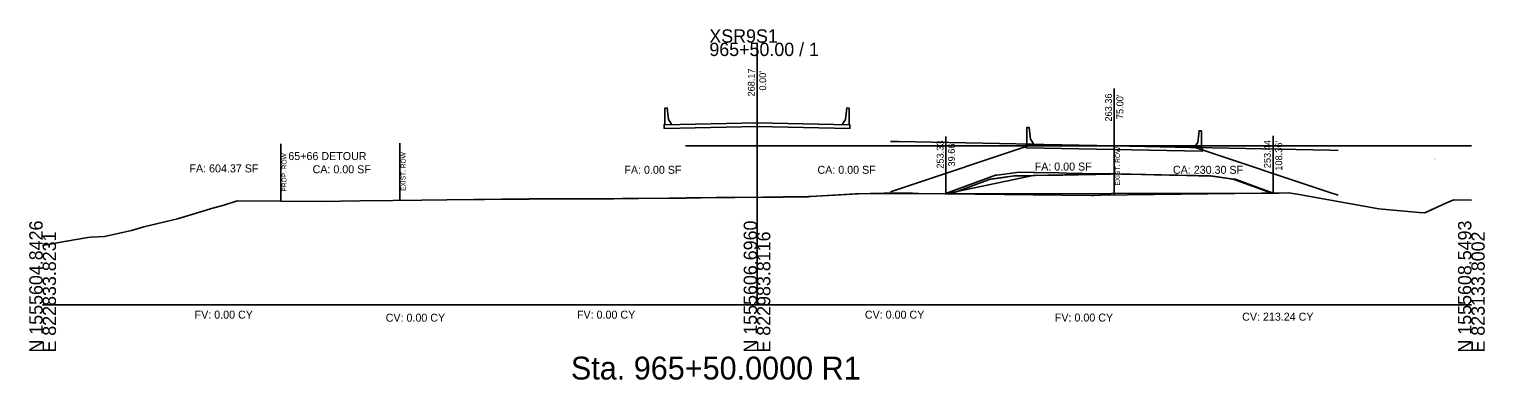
# Model space of a CAD drawing. Extents: x -26 to 823017, y -16 to 1558356.
# Drawn here: x 997.2 to 1302.8, y 4984.3 to 5057.8 of the extents above; entities that cross this region are included whole.
import ezdxf

# ---------------------------------------------------------------- set-up
doc = ezdxf.new("R2010")
doc.units = 0
for name, color, linetype in [('CONST_LV3', 7, 'Continuous'), ('Draft_XS_Grid', 7, 'Continuous'), ('Draft_XS_Text', 7, 'Continuous'), ('DTM_TEMP_DROP', 7, 'Continuous'), ('DTM_X_GROUND', 7, 'Continuous'), ('X_PROFILES_1', 7, 'Continuous'), ('XS_CELL', 7, 'Continuous'), ('XS_P_CONCRETE', 7, 'Continuous'), ('XS_P_GROUND', 7, 'Continuous'), ('XS_P_NULL_POINT', 7, 'Continuous'), ('XS_P_ROW', 7, 'Continuous'), ('XS_P_SUBGRADE_UNDERCUT', 7, 'Continuous'), ('XS_P_TX_CLEARZONE', 7, 'Continuous'), ('XS_SHEET_EW_TX_AREA', 7, 'Continuous'), ('XS_SHEET_EW_TX_VOLUME', 7, 'Continuous'), ('XS_X_ROW', 7, 'Continuous')]:
    doc.layers.add(name, color=color, linetype=linetype)

msp = doc.modelspace()

# ---------------------------------------------------------------- linework, layer by layer
at = {"layer": 'CONST_LV3'}
for points in [[(1135, 5033.36), (1300, 5033.36)], [(1178, 5034.3), (1179.73, 5034.26), (1208, 5033.7), (1208.98, 5033.68), (1225, 5033.36), (1241.02, 5033.04), (1242, 5033.02), (1270.27, 5032.45), (1272, 5032.42)], [(1178, 5023.7), (1179.73, 5024.28), (1208, 5033.7), (1208.98, 5033.68), (1225, 5033.36), (1241.02, 5033.04), (1242, 5033.02), (1270.27, 5023.6), (1272, 5023.02)], [(1000, 5012.44), (1005.04, 5013.35), (1009.5, 5014.16), (1010.12, 5014.21), (1012.96, 5014.34), (1018.65, 5015.63), (1021.23, 5016.35), (1028.33, 5018.07), (1035.97, 5020.35), (1037.84, 5020.84), (1040.84, 5021.8), (1050.02, 5021.76), (1058.5, 5021.71), (1066.61, 5021.81), (1073.56, 5021.9), (1079.59, 5021.97), (1084.87, 5022.03), (1100.77, 5022.2), (1102.16, 5022.22), (1111.63, 5022.24), (1111.86, 5022.24), (1118.28, 5022.23), (1118.45, 5022.23), (1118.74, 5022.24), (1119.81, 5022.27), (1119.96, 5022.28), (1121.71, 5022.34), (1124.87, 5022.33), (1124.89, 5022.33), (1125.13, 5022.34), (1131.5, 5022.42), (1131.5, 5022.42), (1135.22, 5022.44), (1141.41, 5022.52), (1141.41, 5022.52), (1145.28, 5022.54), (1145.31, 5022.54), (1151.32, 5022.62), (1151.32, 5022.62), (1155.39, 5022.63), (1160.81, 5022.7), (1161.24, 5022.71), (1170.63, 5023.29), (1171.28, 5023.33), (1173.79, 5023.34), (1176.66, 5023.44), (1177.7, 5023.47), (1181.91, 5023.42), (1182.64, 5023.41), (1183.67, 5023.4), (1183.69, 5023.4), (1183.94, 5023.4), (1189.42, 5023.33), (1190.69, 5023.32), (1198.96, 5026.35), (1199.2, 5026.39), (1201.37, 5026.68), (1204.02, 5027.04), (1204.53, 5027.05), (1205, 5027.06), (1206.57, 5027.09), (1208, 5027.12), (1208.2, 5027.12), (1208.38, 5027.12), (1211.04, 5027.18), (1211.77, 5027.19), (1213.38, 5027.22), (1214.25, 5027.24), (1214.56, 5027.25), (1215, 5027.26), (1216.82, 5027.29), (1217.46, 5027.31), (1218.38, 5027.32), (1221.08, 5027.38), (1222.1, 5027.4), (1223.38, 5027.42), (1224.26, 5027.44), (1224.91, 5027.46), (1225, 5027.46), (1226.55, 5027.43), (1228.38, 5027.39), (1228.56, 5027.39), (1230.75, 5027.34), (1233.38, 5027.29), (1234.16, 5027.27), (1235, 5027.26), (1236.65, 5027.22), (1238.38, 5027.19), (1240.19, 5027.15), (1242, 5027.12), (1242.7, 5027.1), (1243.38, 5027.09), (1244.21, 5027.07), (1245, 5027.06), (1245.01, 5027.06), (1245.01, 5027.06), (1245.16, 5027.04), (1249.85, 5026.41), (1250.07, 5026.37), (1254.88, 5024.61), (1258.08, 5023.44), (1259.6, 5023.45), (1261.7, 5023.48), (1263.45, 5023.24), (1280.6, 5020.14), (1289.02, 5019.4), (1290.24, 5019.29), (1294.62, 5021.37), (1296.3, 5022.03), (1300, 5021.94)], [(1189.66, 5023.33), (1189.66, 5023.33), (1208, 5027.12)]]:
    msp.add_lwpolyline(points, dxfattribs=at)
at = {"layer": 'DTM_X_GROUND'}
for points in [[(1000, 5012.44), (1005.04, 5013.35), (1009.5, 5014.16), (1010.12, 5014.21), (1012.96, 5014.34), (1018.65, 5015.63), (1021.23, 5016.35), (1028.33, 5018.07), (1035.97, 5020.35), (1037.84, 5020.84), (1040.84, 5021.8), (1050.02, 5021.76), (1058.5, 5021.71), (1066.61, 5021.81), (1073.56, 5021.9), (1079.59, 5021.97), (1084.87, 5022.03), (1102.16, 5022.22), (1111.86, 5022.24), (1118.45, 5022.23), (1121.71, 5022.34), (1124.89, 5022.33), (1125.13, 5022.34), (1131.5, 5022.42), (1135.22, 5022.44), (1141.41, 5022.52), (1145.31, 5022.54), (1151.32, 5022.62), (1155.39, 5022.63), (1161.24, 5022.71), (1171.28, 5023.33), (1173.79, 5023.34), (1176.66, 5023.44), (1177.7, 5023.47), (1181.91, 5023.42), (1182.64, 5023.41), (1183.67, 5023.4), (1183.69, 5023.4), (1183.94, 5023.4), (1189.42, 5023.33), (1190.69, 5023.32), (1198.96, 5026.35), (1199.2, 5026.39), (1201.37, 5026.68), (1204.02, 5027.04), (1204.53, 5027.05), (1205, 5027.06), (1206.57, 5027.09), (1208, 5027.12), (1208.2, 5027.12), (1208.38, 5027.12), (1211.04, 5027.18), (1211.77, 5027.19), (1213.38, 5027.22), (1214.25, 5027.24), (1214.56, 5027.25), (1215, 5027.26), (1216.82, 5027.29), (1217.46, 5027.31), (1218.38, 5027.32), (1221.08, 5027.38), (1222.1, 5027.4), (1223.38, 5027.42), (1224.26, 5027.44), (1224.91, 5027.46), (1225, 5027.46), (1226.55, 5027.43), (1228.38, 5027.39), (1228.56, 5027.39), (1230.75, 5027.34), (1233.38, 5027.29), (1234.16, 5027.27), (1235, 5027.26), (1236.65, 5027.22), (1238.38, 5027.19), (1240.19, 5027.15), (1242, 5027.12), (1242.7, 5027.1), (1243.38, 5027.09), (1244.21, 5027.07), (1245, 5027.06), (1245.01, 5027.06), (1245.01, 5027.06), (1245.16, 5027.04), (1249.85, 5026.41), (1250.07, 5026.37), (1254.88, 5024.61), (1258.08, 5023.44), (1259.6, 5023.45), (1261.7, 5023.48), (1263.45, 5023.24), (1280.6, 5020.14), (1289.02, 5019.4), (1290.24, 5019.29), (1294.62, 5021.37), (1296.3, 5022.03), (1300, 5021.94)], [(1000, 5012.44), (1005.04, 5013.35), (1009.5, 5014.16), (1010.12, 5014.21), (1012.96, 5014.34), (1018.65, 5015.63), (1021.23, 5016.35), (1028.33, 5018.07), (1035.97, 5020.35), (1037.84, 5020.84), (1040.84, 5021.8), (1050.02, 5021.76), (1058.5, 5021.71), (1066.61, 5021.81), (1073.56, 5021.9), (1079.59, 5021.97), (1084.87, 5022.03), (1100.77, 5022.18), (1102.16, 5022.21), (1111.63, 5022.23), (1111.86, 5022.24), (1118.28, 5022.22), (1118.45, 5022.23), (1118.74, 5022.24), (1119.81, 5022.27), (1119.96, 5022.28), (1121.71, 5022.3), (1124.87, 5022.29), (1124.89, 5022.29), (1125.13, 5022.29), (1131.5, 5022.38), (1131.5, 5022.38), (1135.22, 5022.41), (1141.41, 5022.5), (1141.41, 5022.5), (1145.28, 5022.54), (1145.31, 5022.54), (1151.32, 5022.62), (1151.32, 5022.62), (1155.39, 5022.68), (1160.81, 5022.76), (1161.24, 5022.76), (1170.63, 5023.33), (1171.28, 5023.33), (1173.79, 5023.35), (1176.66, 5023.36), (1177.7, 5023.37), (1181.91, 5023.39), (1182.64, 5023.4), (1183.67, 5023.4), (1183.69, 5023.4), (1183.94, 5023.4), (1189.42, 5023.33), (1190.69, 5023.32), (1198.96, 5026.35), (1199.2, 5026.39), (1201.37, 5026.68), (1204.02, 5027.04), (1204.53, 5027.05), (1205, 5027.06), (1206.57, 5027.09), (1208, 5027.12), (1208.2, 5027.12), (1208.38, 5027.12), (1211.04, 5027.18), (1211.77, 5027.19), (1213.38, 5027.22), (1214.25, 5027.24), (1214.56, 5027.25), (1215, 5027.26), (1216.82, 5027.29), (1217.46, 5027.31), (1218.38, 5027.32), (1221.08, 5027.38), (1222.1, 5027.4), (1223.38, 5027.42), (1224.26, 5027.44), (1224.91, 5027.46), (1225, 5027.46), (1226.55, 5027.43), (1228.38, 5027.39), (1228.56, 5027.39), (1230.75, 5027.34), (1233.38, 5027.29), (1234.16, 5027.27), (1235, 5027.26), (1236.65, 5027.22), (1238.38, 5027.19), (1240.19, 5027.15), (1242, 5027.12), (1242.7, 5027.1), (1243.38, 5027.09), (1244.21, 5027.07), (1245, 5027.06), (1245.01, 5027.06), (1245.01, 5027.06), (1245.16, 5027.04), (1249.85, 5026.41), (1250.07, 5026.37), (1254.88, 5024.61), (1258.08, 5023.44), (1259.6, 5023.45), (1261.7, 5023.48), (1263.45, 5023.24), (1280.6, 5020.14), (1289.02, 5019.4), (1290.24, 5019.29), (1294.62, 5021.37), (1296.3, 5022.03), (1300, 5021.94)], [(1000, 5012.44), (1005.04, 5013.35), (1009.5, 5014.16), (1010.12, 5014.21), (1012.96, 5014.34), (1018.65, 5015.63), (1021.23, 5016.35), (1028.33, 5018.07), (1035.97, 5020.35), (1037.84, 5020.84), (1040.84, 5021.8), (1050.02, 5021.76), (1058.5, 5021.71), (1066.61, 5021.81), (1073.56, 5021.9), (1079.59, 5021.97), (1084.87, 5022.03), (1102.16, 5022.22), (1111.86, 5022.24), (1118.45, 5022.23), (1121.71, 5022.34), (1124.89, 5022.33), (1125.13, 5022.34), (1131.5, 5022.42), (1135.22, 5022.44), (1141.41, 5022.52), (1145.31, 5022.54), (1151.32, 5022.62), (1155.39, 5022.63), (1161.24, 5022.71), (1171.28, 5023.33), (1173.79, 5023.34), (1176.66, 5023.44), (1177.7, 5023.47), (1220.21, 5022.97), (1220.35, 5022.97), (1220.38, 5022.97), (1220.4, 5022.97), (1220.43, 5022.97), (1220.47, 5022.97), (1220.5, 5022.97), (1220.67, 5022.97), (1222.09, 5022.99), (1261.7, 5023.48), (1263.45, 5023.24), (1280.6, 5020.14), (1289.02, 5019.4), (1290.24, 5019.29), (1294.62, 5021.37), (1296.3, 5022.03), (1300, 5021.94)]]:
    msp.add_lwpolyline(points, dxfattribs=at)
at = {"layer": 'XS_CELL'}
for p, q in [((1150, 5000), (1150, 5055)), ((1000, 5000), (1150, 5000)), ((1150, 5000), (1300, 5000))]:
    msp.add_line(p, q, dxfattribs=at)
at = {"layer": 'XS_P_CONCRETE'}
for points in [[(1130.67, 5037.78), (1130.67, 5041.28), (1131.17, 5041.31), (1131.42, 5038.89), (1132, 5038.06), (1132, 5037.81), (1130.67, 5037.78)], [(1169.33, 5037.78), (1169.33, 5041.28), (1168.83, 5041.31), (1168.58, 5038.89), (1168, 5038.06), (1168, 5037.81), (1169.33, 5037.78)], [(1150, 5038.17), (1169.33, 5037.78), (1169.5, 5037.78), (1169.5, 5037.03), (1150, 5037.42), (1130.5, 5037.03), (1130.5, 5037.78), (1130.67, 5037.78), (1150, 5038.17)], [(1206.67, 5033.73), (1206.67, 5037.23), (1207.17, 5037.2), (1207.42, 5034.78), (1208, 5033.95), (1208, 5033.7), (1206.67, 5033.73)], [(1243.33, 5032.99), (1243.33, 5036.49), (1242.83, 5036.52), (1242.58, 5034.1), (1242, 5033.27), (1242, 5033.02), (1243.33, 5032.99)], [(1225, 5033.36), (1243.33, 5032.99), (1243.5, 5032.99), (1243.5, 5032.24), (1225, 5032.61), (1206.5, 5032.98), (1206.5, 5033.73), (1206.67, 5033.73), (1225, 5033.36)]]:
    msp.add_lwpolyline(points, dxfattribs=at)
at = {"layer": 'XS_P_GROUND'}
for points in [[(1189.66, 5023.33), (1189.96, 5023.48), (1189.98, 5023.49), (1200.09, 5027.18), (1200.36, 5027.22), (1205.15, 5027.85)], [(1245.32, 5027.05), (1245, 5027.06), (1243.38, 5027.09), (1242, 5027.12), (1238.38, 5027.19), (1235, 5027.26), (1233.38, 5027.29), (1228.38, 5027.39), (1225, 5027.46), (1223.38, 5027.49), (1218.38, 5027.59), (1215, 5027.66), (1213.38, 5027.69), (1208.38, 5027.79), (1208, 5027.8), (1205.15, 5027.85)], [(1245.32, 5027.05), (1250.15, 5026.4), (1250.38, 5026.37), (1250.6, 5026.28), (1258.36, 5023.44)], [(1189.66, 5023.33), (1189.66, 5023.33), (1220.21, 5022.97), (1220.21, 5022.97), (1220.21, 5022.97), (1220.21, 5022.97), (1220.35, 5022.97), (1220.38, 5022.97), (1220.4, 5022.97), (1220.43, 5022.97), (1220.47, 5022.97), (1220.5, 5022.97), (1220.67, 5022.97), (1222.09, 5022.99), (1222.09, 5022.99), (1222.09, 5022.99), (1261.7, 5023.48), (1261.7, 5023.48), (1263.45, 5023.24), (1263.45, 5023.24), (1280.6, 5020.14), (1280.6, 5020.14), (1280.6, 5020.14), (1289.02, 5019.4), (1289.02, 5019.4), (1290.24, 5019.29), (1292.3, 5020.27)], [(1189.66, 5023.33), (1189.66, 5023.33), (1220.21, 5022.97), (1220.21, 5022.97), (1220.21, 5022.97), (1220.21, 5022.97), (1220.35, 5022.97), (1220.38, 5022.97), (1220.4, 5022.97), (1220.43, 5022.97), (1220.47, 5022.97), (1220.5, 5022.97), (1220.67, 5022.97), (1222.09, 5022.99), (1222.09, 5022.99), (1222.09, 5022.99), (1261.7, 5023.48), (1261.7, 5023.48), (1263.45, 5023.24), (1263.45, 5023.24), (1280.6, 5020.14), (1280.6, 5020.14), (1280.6, 5020.14), (1289.02, 5019.4), (1289.02, 5019.4), (1290.24, 5019.29), (1292.3, 5020.27)]]:
    msp.add_lwpolyline(points, dxfattribs=at)
at = {"layer": 'XS_P_ROW'}
msp.add_line((1050, 5021.76), (1050, 5033.76), dxfattribs=at)
at = {"layer": 'XS_P_SUBGRADE_UNDERCUT'}
msp.add_lwpolyline([(1190.69, 5023.32), (1198.96, 5026.35), (1204.02, 5027.04), (1208.38, 5027.12), (1225, 5027.46), (1245, 5027.06), (1249.96, 5026.39), (1258.08, 5023.44)], close=True, dxfattribs=at)
at = {"layer": 'XS_P_TX_CLEARZONE'}
for p, q in [((1150, 5038.17), (1150, 5050.17)), ((1225, 5033.36), (1225, 5045.36)), ((1189.66, 5023.33), (1189.66, 5035.33)), ((1258.36, 5023.44), (1258.36, 5035.44))]:
    msp.add_line(p, q, dxfattribs=at)
at = {"layer": 'XS_X_ROW'}
for p, q in [((1225, 5023.03), (1225, 5035.03)), ((1075, 5021.91), (1075, 5033.91))]:
    msp.add_line(p, q, dxfattribs=at)

# ---------------------------------------------------------------- texts
at = {"layer": 'CONST_LV3'}
for p in [(1292.22, 5030.55), (1189.58, 5023.21)]:
    msp.add_text('X', height=0.24, dxfattribs=at).set_placement(p)
at = {"layer": 'Draft_XS_Grid'}
msp.add_text('-', height=0.0001, dxfattribs=at).set_placement((1000, 5000))
at = {"layer": 'Draft_XS_Text'}
msp.add_text('Sta. 965+50.0000 R1', height=4.8, dxfattribs=at).set_placement((1110.92, 4984.35))
at = {"layer": 'DTM_TEMP_DROP'}
for p in [(1149.92, 5038.05), (1224.92, 5033.24)]:
    msp.add_text('X', height=0.24, dxfattribs=at).set_placement(p)
at = {"layer": 'X_PROFILES_1'}
msp.add_text('X', height=0.24, dxfattribs=at).set_placement((1189.58, 5023.21))
at = {"layer": 'XS_CELL'}
for s, p in [('XSR9S1', (1140, 5055)), ('965+50.00 / 1', (1140, 5052.2))]:
    msp.add_text(s, height=2.8, dxfattribs=at).set_placement(p)
for s, p in [('N 1555604.8426', (1000, 4990)), ('N 1555606.6960', (1150, 4990)), ('N 1555608.5493', (1300, 4990)), ('E 822833.8231', (1002.8, 4990)), ('E 822983.8116', (1152.8, 4990)), ('E 823133.8002', (1302.8, 4990))]:
    msp.add_text(s, height=2.8, rotation=90, dxfattribs=at).set_placement(p)
at = {"layer": 'XS_P_NULL_POINT'}
for p in [(1189.58, 5023.21), (1258.28, 5023.32)]:
    msp.add_text('X', height=0.24, dxfattribs=at).set_placement(p)
at = {"layer": 'XS_P_ROW'}
msp.add_text('PROP. ROW', height=1, rotation=90, dxfattribs=at).set_placement((1051.2, 5023.76))
at = {"layer": 'XS_P_TX_CLEARZONE'}
for s, p in [('268.17', (1149.52, 5043.71)), ("0.00'", (1151.92, 5044.96)), ('263.36', (1224.52, 5038.46)), ("75.00'", (1226.92, 5038.97)), ('253.33', (1189.18, 5028.58)), ("39.66'", (1191.58, 5029.03)), ('253.44', (1257.88, 5028.68)), ("108.36'", (1260.28, 5028.16))]:
    msp.add_text(s, height=1.44, rotation=90, dxfattribs=at).set_placement(p)
at = {"layer": 'XS_SHEET_EW_TX_AREA'}
for s, p in [('65+66 DETOUR', (1051.59, 5030.38)), ('FA: 604.37 SF', (1030.83, 5027.79)), ('CA: 0.00 SF', (1056.68, 5027.61)), ('FA: 0.00 SF', (1122.15, 5027.5)), ('CA: 0.00 SF', (1162.7, 5027.5)), ('FA: 0.00 SF', (1208.3, 5028.18)), ('CA: 230.30 SF', (1237.34, 5027.5))]:
    msp.add_text(s, height=1.68, dxfattribs=at).set_placement(p)
at = {"layer": 'XS_SHEET_EW_TX_VOLUME'}
for s, p in [('FV: 0.00 CY', (1031.91, 4997.12)), ('CV: 0.00 CY', (1072.03, 4996.48)), ('FV: 0.00 CY', (1112.2, 4997.12)), ('CV: 0.00 CY', (1172.65, 4997.12)), ('FV: 0.00 CY', (1212.54, 4996.51)), ('CV: 213.24 CY', (1251.87, 4996.69))]:
    msp.add_text(s, height=1.68, dxfattribs=at).set_placement(p)
at = {"layer": 'XS_X_ROW'}
for p in [(1076.2, 5023.91), (1226.2, 5025.03)]:
    msp.add_text('EXIST. ROW', height=1, rotation=90, dxfattribs=at).set_placement(p)

doc.saveas('drawing.dxf')
